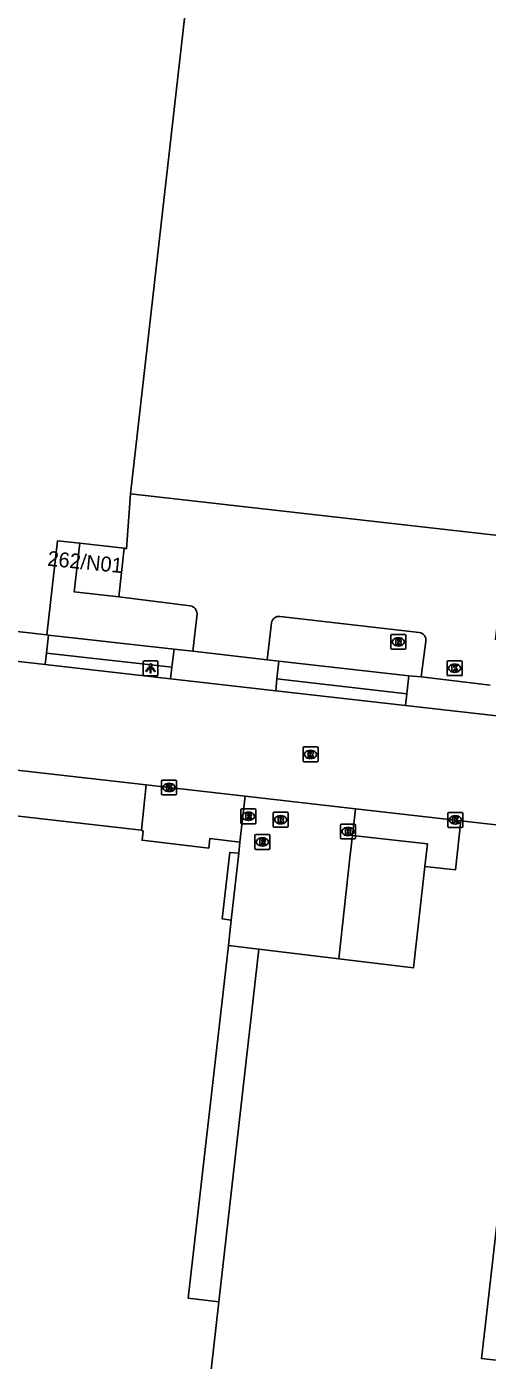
# Model space of a CAD drawing. Extents: x 161389 to 162585, y 388479 to 389761.
# Drawn here: x 162433.2 to 162464.1, y 388747.2 to 388836.7 of the extents above; entities that cross this region are included whole.
import ezdxf

# ---------------------------------------------------------------- set-up
doc = ezdxf.new("R2010")
doc.units = 0
for name, color, linetype in [('IMGEO_Groenvoorziening', 7, 'Continuous'), ('IMGEO_Kolk', 7, 'Continuous'), ('IMGEO_Lichtpunt', 7, 'Continuous'), ('IMGEO_Pand', 7, 'Continuous'), ('IMGEO_Pand_nummerreeks', 7, 'Continuous'), ('IMGEO_Pand_overbouw', 7, 'Continuous'), ('IMGEO_Parkeervlak_open', 7, 'Continuous'), ('IMGEO_Rijbaan_lokaal_gesloten', 7, 'Continuous'), ('IMGEO_Rioolput', 7, 'Continuous'), ('IMGEO_Voetpad_open', 7, 'Continuous')]:
    doc.layers.add(name, color=color, linetype=linetype)

msp = doc.modelspace()

# ---------------------------------------------------------------- linework, layer by layer
at = {"layer": 'IMGEO_Groenvoorziening'}
for points in [[(162436.753, 388802.017), (162435.263, 388802.18), (162434.552, 388795.859)], [(162459.918, 388780.324), (162461.966, 388780.093), (162462.337, 388783.374)]]:
    msp.add_lwpolyline(points, dxfattribs=at)
at = {"layer": 'IMGEO_Kolk'}
for p, q in [((162461.414, 388793.197), (162461.414, 388794.049)), ((162461.489, 388794.123), (162462.341, 388794.123)), ((162461.902, 388793.903), (162461.927, 388793.903)), ((162462.415, 388794.049), (162462.415, 388793.197)), ((162462.341, 388793.123), (162461.489, 388793.123)), ((162461.925, 388793.343), (162461.9, 388793.343)), ((162442.249, 388785.195), (162442.249, 388786.047)), ((162442.324, 388786.121), (162443.176, 388786.121)), ((162442.76, 388785.341), (162442.735, 388785.341)), ((162442.737, 388785.901), (162442.762, 388785.901)), ((162443.25, 388786.047), (162443.25, 388785.195)), ((162443.176, 388785.121), (162442.324, 388785.121)), ((162461.462, 388783.018), (162461.462, 388783.87)), ((162461.537, 388783.944), (162462.389, 388783.944)), ((162461.95, 388783.724), (162461.975, 388783.724)), ((162462.463, 388783.87), (162462.463, 388783.018)), ((162462.389, 388782.944), (162461.537, 388782.944)), ((162461.973, 388783.164), (162461.948, 388783.164))]:
    msp.add_line(p, q, dxfattribs=at)
for points in [[(162461.414, 388793.197), (162461.414, 388794.049)], [(162461.489, 388794.123), (162462.341, 388794.123)], [(162461.735, 388793.823), (162461.858, 388793.823), (162461.858, 388793.672), (162461.988, 388793.823), (162462.152, 388793.823), (162462.006, 388793.672), (162462.159, 388793.423), (162462.007, 388793.423), (162461.922, 388793.587), (162461.858, 388793.52), (162461.858, 388793.423), (162461.735, 388793.423), (162461.735, 388793.823)], [(162462.415, 388794.049), (162462.415, 388793.197)], [(162462.341, 388793.123), (162461.489, 388793.123)], [(162442.249, 388785.195), (162442.249, 388786.047)], [(162442.324, 388786.121), (162443.176, 388786.121)], [(162442.57, 388785.821), (162442.693, 388785.821), (162442.693, 388785.67), (162442.823, 388785.821), (162442.987, 388785.821), (162442.841, 388785.67), (162442.994, 388785.421), (162442.842, 388785.421), (162442.757, 388785.585), (162442.693, 388785.518), (162442.693, 388785.421), (162442.57, 388785.421), (162442.57, 388785.821)], [(162443.25, 388786.047), (162443.25, 388785.195)], [(162443.176, 388785.121), (162442.324, 388785.121)], [(162461.462, 388783.018), (162461.462, 388783.87)], [(162461.537, 388783.944), (162462.389, 388783.944)], [(162461.783, 388783.644), (162461.906, 388783.644), (162461.906, 388783.493), (162462.036, 388783.644), (162462.2, 388783.644), (162462.054, 388783.493), (162462.207, 388783.244), (162462.055, 388783.244), (162461.97, 388783.408), (162461.906, 388783.341), (162461.906, 388783.244), (162461.783, 388783.244), (162461.783, 388783.644)], [(162462.463, 388783.87), (162462.463, 388783.018)], [(162462.389, 388782.944), (162461.537, 388782.944)]]:
    msp.add_lwpolyline(points, dxfattribs=at)
for centre, start, end in [((162461.491, 388794.047), 91.55205, 178.44795), ((162461.491, 388794.047), 91.55205, 178.44795), ((162462.339, 388794.047), 1.55205, 88.44795), ((162462.339, 388794.047), 1.55205, 88.44795), ((162461.491, 388793.199), 181.55205, 268.44795), ((162461.491, 388793.199), 181.55205, 268.44795), ((162462.339, 388793.199), 271.55205, 358.44795), ((162462.339, 388793.199), 271.55205, 358.44795), ((162442.326, 388786.045), 91.55205, 178.44795), ((162442.326, 388786.045), 91.55205, 178.44795), ((162443.174, 388786.045), 1.55205, 88.44795), ((162443.174, 388786.045), 1.55205, 88.44795), ((162442.326, 388785.197), 181.55205, 268.44795), ((162442.326, 388785.197), 181.55205, 268.44795), ((162443.174, 388785.197), 271.55205, 358.44795), ((162443.174, 388785.197), 271.55205, 358.44795), ((162461.539, 388783.868), 91.55205, 178.44795), ((162461.539, 388783.868), 91.55205, 178.44795), ((162462.387, 388783.868), 1.55205, 88.44795), ((162462.387, 388783.868), 1.55205, 88.44795), ((162461.539, 388783.02), 181.55205, 268.44795), ((162461.539, 388783.02), 181.55205, 268.44795), ((162462.387, 388783.02), 271.55205, 358.44795), ((162462.387, 388783.02), 271.55205, 358.44795)]:
    msp.add_arc(centre, 0.0765, start, end, dxfattribs=at)
for centre, major_axis, ratio, start_param, end_param in [((162461.901, 388793.623), (-0.387, 0.002), 0.722429, 4.712389, 7.853982), ((162461.926, 388793.623), (-0.39, 0.002), 0.717154, 1.570796, 4.712389), ((162442.736, 388785.621), (-0.387, 0.002), 0.722429, 4.712389, 7.853982), ((162442.761, 388785.621), (-0.39, 0.002), 0.717154, 1.570796, 4.712389), ((162461.949, 388783.444), (-0.387, 0.002), 0.722429, 4.712389, 7.853982), ((162461.974, 388783.444), (-0.39, 0.002), 0.717154, 1.570796, 4.712389)]:
    msp.add_ellipse(centre, major_axis=major_axis, ratio=ratio, start_param=start_param, end_param=end_param, dxfattribs=at)
at = {"layer": 'IMGEO_Lichtpunt'}
for p, q in [((162441.005, 388794.019), (162441.005, 388793.212)), ((162441.005, 388794.019), (162441.005, 388793.212)), ((162441.907, 388794.114), (162441.099, 388794.114)), ((162441.907, 388794.114), (162441.099, 388794.114)), ((162442.001, 388793.212), (162442.001, 388794.019)), ((162442.001, 388793.212), (162442.001, 388794.019)), ((162441.099, 388793.118), (162441.907, 388793.118)), ((162441.099, 388793.118), (162441.907, 388793.118))]:
    msp.add_line(p, q, dxfattribs=at)
for points in [[(162441.379, 388793.683), (162441.418, 388793.655), (162441.23, 388793.393), (162441.192, 388793.42), (162441.379, 388793.683)], [(162441.481, 388793.635), (162441.528, 388793.635), (162441.528, 388793.313), (162441.481, 388793.313), (162441.481, 388793.635)], [(162441.591, 388793.655), (162441.629, 388793.682), (162441.816, 388793.42), (162441.777, 388793.392), (162441.591, 388793.655)]]:
    msp.add_lwpolyline(points, dxfattribs=at)
msp.add_circle((162441.504, 388793.817), 0.0994, dxfattribs=at)
for centre, start, end in [((162441.099, 388794.019), 90, 180), ((162441.099, 388794.019), 90, 180), ((162441.907, 388794.019), 0, 90), ((162441.907, 388794.019), 0, 90), ((162441.099, 388793.212), 180, 270), ((162441.099, 388793.212), 180, 270), ((162441.907, 388793.212), 270, 0), ((162441.907, 388793.212), 270, 360)]:
    msp.add_arc(centre, 0.0946, start, end, dxfattribs=at)
at = {"layer": 'IMGEO_Pand'}
for points in [[(162440.168, 388805.317), (162445.286, 388850.441), (162482.306, 388846.26), (162482.466, 388837.077), (162482.487, 388836.004), (162487.823, 388836.098), (162489.492, 388836.131)], [(162440.168, 388805.317), (162465.452, 388802.451), (162464.664, 388795.518)], [(162439.367, 388798.403), (162436.385, 388798.738), (162436.753, 388802.017)], [(162436.753, 388802.017), (162439.735, 388801.682)], [(162439.735, 388801.682), (162439.367, 388798.403)], [(162440.896, 388782.752), (162414.734, 388785.722)], [(162447.5, 388781.959), (162445.494, 388782.197), (162445.411, 388781.558), (162440.936, 388782.073), (162441.007, 388782.699), (162440.896, 388782.752)], [(162447.5, 388781.959), (162447.432, 388781.205)], [(162446.92, 388776.723), (162446.311, 388776.801), (162446.824, 388781.26), (162447.432, 388781.205)], [(162484.257, 388737.573), (162484.131, 388744.901), (162484.124, 388745.295), (162484.388, 388745.288), (162484.585, 388747.086), (162480.19, 388747.631), (162479.955, 388745.444), (162463.726, 388747.292), (162464.034, 388750), (162466.634, 388772.833), (162483.618, 388770.935), (162483.585, 388770.043), (162488.919, 388770.194), (162488.998, 388770.12), (162491.396, 388770.192), (162492.166, 388776.206), (162489.637, 388776.512), (162489.631, 388777.339)], [(162446.92, 388776.723), (162446.744, 388775.005)], [(162446.744, 388775.005), (162444.021, 388751.356), (162446.098, 388751.105), (162443.362, 388726.917), (162438.974, 388727.412)]]:
    msp.add_lwpolyline(points, dxfattribs=at)
at = {"layer": 'IMGEO_Pand_overbouw'}
for points in [[(162447.432, 388781.205), (162446.824, 388781.26), (162446.311, 388776.801), (162446.92, 388776.723)], [(162446.098, 388751.105), (162448.766, 388774.777), (162446.744, 388775.005), (162444.021, 388751.356)]]:
    msp.add_lwpolyline(points, close=True, dxfattribs=at)
at = {"layer": 'IMGEO_Parkeervlak_open'}
for points in [[(162439.735, 388801.682), (162439.879, 388801.637), (162440.168, 388805.317)], [(162444.17, 388797.808), (162439.367, 388798.403)], [(162444.338, 388794.771), (162444.626, 388797.272)], [(162450.197, 388797.095), (162459.544, 388796.016)], [(162449.338, 388794.177), (162449.624, 388796.661)], [(162459.984, 388795.44), (162459.672, 388793.036)], [(162455.059, 388782.406), (162460.087, 388781.849), (162459.918, 388780.324)], [(162454.133, 388774.13), (162459.164, 388773.524), (162459.918, 388780.324)]]:
    msp.add_lwpolyline(points, dxfattribs=at)
for centre, radius, start, end in [((162444.089, 388797.277), 0.537, 359.47863, 81.30007), ((162450.123, 388796.597), 0.503, 81.58842, 172.6934), ((162459.485, 388795.515), 0.505, 351.49134, 83.26028)]:
    msp.add_arc(centre, radius, start, end, dxfattribs=at)
at = {"layer": 'IMGEO_Rijbaan_lokaal_gesloten'}
for points in [[(162434.425, 388793.87), (162423.146, 388795.15)], [(162442.854, 388792.912), (162434.425, 388793.87)], [(162449.905, 388792.112), (162442.854, 388792.912)], [(162458.615, 388791.123), (162449.905, 388792.112)], [(162464.75, 388790.426), (162458.615, 388791.123)], [(162415.064, 388788.76), (162424.047, 388787.734), (162441.217, 388785.796)], [(162441.217, 388785.796), (162442.75, 388785.623), (162447.857, 388785.036)], [(162447.857, 388785.036), (162455.264, 388784.185)], [(162455.264, 388784.185), (162461.961, 388783.416), (162462.337, 388783.374)], [(162462.337, 388783.374), (162471.602, 388782.341)]]:
    msp.add_lwpolyline(points, dxfattribs=at)
at = {"layer": 'IMGEO_Rioolput'}
for p, q in [((162457.635, 388794.966), (162457.635, 388795.818)), ((162457.71, 388795.892), (162458.562, 388795.892)), ((162458.123, 388795.672), (162458.148, 388795.672)), ((162458.636, 388795.818), (162458.636, 388794.966)), ((162458.562, 388794.892), (162457.71, 388794.892)), ((162458.146, 388795.112), (162458.121, 388795.112)), ((162451.743, 388787.412), (162451.743, 388788.264)), ((162451.818, 388788.338), (162452.67, 388788.338)), ((162452.231, 388788.118), (162452.256, 388788.118)), ((162452.744, 388788.264), (162452.744, 388787.412)), ((162452.67, 388787.338), (162451.818, 388787.338)), ((162452.254, 388787.558), (162452.229, 388787.558)), ((162447.573, 388783.26), (162447.573, 388784.112)), ((162447.648, 388784.186), (162448.5, 388784.186)), ((162448.061, 388783.966), (162448.086, 388783.966)), ((162448.574, 388784.112), (162448.574, 388783.26)), ((162449.737, 388783.03), (162449.737, 388783.882)), ((162449.812, 388783.956), (162450.664, 388783.956)), ((162450.225, 388783.736), (162450.25, 388783.736)), ((162450.738, 388783.882), (162450.738, 388783.03)), ((162448.5, 388783.186), (162447.648, 388783.186)), ((162448.084, 388783.406), (162448.059, 388783.406)), ((162450.664, 388782.956), (162449.812, 388782.956)), ((162450.248, 388783.176), (162450.223, 388783.176)), ((162454.26, 388782.239), (162454.26, 388783.091)), ((162454.335, 388783.165), (162455.187, 388783.165)), ((162454.748, 388782.945), (162454.773, 388782.945)), ((162455.261, 388783.091), (162455.261, 388782.239)), ((162448.513, 388781.538), (162448.513, 388782.39)), ((162448.588, 388782.464), (162449.44, 388782.464)), ((162449.001, 388782.244), (162449.026, 388782.244)), ((162449.514, 388782.39), (162449.514, 388781.538)), ((162455.187, 388782.165), (162454.335, 388782.165)), ((162454.771, 388782.385), (162454.746, 388782.385)), ((162449.44, 388781.464), (162448.588, 388781.464)), ((162449.024, 388781.684), (162448.999, 388781.684))]:
    msp.add_line(p, q, dxfattribs=at)
for points in [[(162457.635, 388794.966), (162457.635, 388795.818)], [(162457.71, 388795.892), (162458.562, 388795.892)], [(162458.224, 388795.59), (162457.972, 388795.592), (162457.972, 388795.192)], [(162457.972, 388795.192), (162458.096, 388795.192), (162458.096, 388795.354), (162458.107, 388795.354)], [(162458.15, 388795.511), (162458.096, 388795.511), (162458.096, 388795.43)], [(162458.096, 388795.43), (162458.148, 388795.43)], [(162458.154, 388795.325), (162458.225, 388795.192), (162458.365, 388795.192), (162458.3, 388795.318)], [(162458.636, 388795.818), (162458.636, 388794.966)], [(162458.562, 388794.892), (162457.71, 388794.892)], [(162451.743, 388787.412), (162451.743, 388788.264)], [(162451.818, 388788.338), (162452.67, 388788.338)], [(162452.332, 388788.036), (162452.08, 388788.038), (162452.08, 388787.638)], [(162452.744, 388788.264), (162452.744, 388787.412)], [(162452.67, 388787.338), (162451.818, 388787.338)], [(162452.08, 388787.638), (162452.204, 388787.638), (162452.204, 388787.8), (162452.215, 388787.8)], [(162452.258, 388787.957), (162452.204, 388787.957), (162452.204, 388787.876)], [(162452.204, 388787.876), (162452.256, 388787.876)], [(162452.262, 388787.771), (162452.333, 388787.638), (162452.473, 388787.638), (162452.408, 388787.764)], [(162447.573, 388783.26), (162447.573, 388784.112)], [(162447.648, 388784.186), (162448.5, 388784.186)], [(162448.162, 388783.884), (162447.91, 388783.886), (162447.91, 388783.486)], [(162447.91, 388783.486), (162448.034, 388783.486), (162448.034, 388783.648), (162448.045, 388783.648)], [(162448.088, 388783.805), (162448.034, 388783.805), (162448.034, 388783.724)], [(162448.034, 388783.724), (162448.086, 388783.724)], [(162448.092, 388783.619), (162448.163, 388783.486), (162448.303, 388783.486), (162448.238, 388783.612)], [(162448.574, 388784.112), (162448.574, 388783.26)], [(162449.737, 388783.03), (162449.737, 388783.882)], [(162449.812, 388783.956), (162450.664, 388783.956)], [(162450.326, 388783.654), (162450.074, 388783.656), (162450.074, 388783.256)], [(162450.252, 388783.575), (162450.198, 388783.575), (162450.198, 388783.494)], [(162450.738, 388783.882), (162450.738, 388783.03)], [(162448.5, 388783.186), (162447.648, 388783.186)], [(162450.664, 388782.956), (162449.812, 388782.956)], [(162450.074, 388783.256), (162450.198, 388783.256), (162450.198, 388783.418), (162450.209, 388783.418)], [(162450.198, 388783.494), (162450.25, 388783.494)], [(162450.256, 388783.389), (162450.327, 388783.256), (162450.467, 388783.256), (162450.402, 388783.382)], [(162454.26, 388782.239), (162454.26, 388783.091)], [(162454.335, 388783.165), (162455.187, 388783.165)], [(162454.849, 388782.863), (162454.597, 388782.865), (162454.597, 388782.465)], [(162454.597, 388782.465), (162454.721, 388782.465), (162454.721, 388782.627), (162454.732, 388782.627)], [(162454.775, 388782.784), (162454.721, 388782.784), (162454.721, 388782.703)], [(162454.721, 388782.703), (162454.773, 388782.703)], [(162455.261, 388783.091), (162455.261, 388782.239)], [(162448.513, 388781.538), (162448.513, 388782.39)], [(162448.588, 388782.464), (162449.44, 388782.464)], [(162449.102, 388782.162), (162448.85, 388782.164), (162448.85, 388781.764)], [(162448.85, 388781.764), (162448.974, 388781.764), (162448.974, 388781.926), (162448.985, 388781.926)], [(162449.028, 388782.083), (162448.974, 388782.083), (162448.974, 388782.002)], [(162448.974, 388782.002), (162449.026, 388782.002)], [(162449.032, 388781.897), (162449.103, 388781.764), (162449.243, 388781.764), (162449.178, 388781.89)], [(162449.514, 388782.39), (162449.514, 388781.538)], [(162455.187, 388782.165), (162454.335, 388782.165)], [(162454.779, 388782.598), (162454.85, 388782.465), (162454.99, 388782.465), (162454.925, 388782.591)], [(162449.44, 388781.464), (162448.588, 388781.464)]]:
    msp.add_lwpolyline(points, dxfattribs=at)
for centre, radius, start, end in [((162457.712, 388795.816), 0.0765, 91.55205, 178.44795), ((162457.712, 388795.816), 0.0765, 91.55205, 178.44795), ((162458.106, 388795.301), 0.0533, 26.02933, 88.69889), ((162458.132, 388795.619), 0.19, 274.7715, 282.96867), ((162458.156, 388795.415), 0.0964, 77.00612, 93.18647), ((162458.17, 388795.472), 0.0378, 276.66336, 79.67722), ((162458.223, 388795.48), 0.109, 350.36119, 89.41601), ((162458.221, 388795.48), 0.112, 277.58423, 350.98172), ((162458.205, 388795.265), 0.108, 29.51342, 73.79051), ((162458.56, 388795.816), 0.0765, 1.55205, 88.44795), ((162458.56, 388795.816), 0.0765, 1.55205, 88.44795), ((162457.712, 388794.968), 0.0765, 181.55205, 268.44795), ((162457.712, 388794.968), 0.0765, 181.55205, 268.44795), ((162458.56, 388794.968), 0.0765, 271.55205, 358.44795), ((162458.56, 388794.968), 0.0765, 271.55205, 358.44795), ((162451.82, 388788.262), 0.0765, 91.55205, 178.44795), ((162451.82, 388788.262), 0.0765, 91.55205, 178.44795), ((162452.331, 388787.926), 0.109, 350.36119, 89.41601), ((162452.668, 388788.262), 0.0765, 1.55205, 88.44795), ((162452.668, 388788.262), 0.0765, 1.55205, 88.44795), ((162451.82, 388787.414), 0.0765, 181.55205, 268.44795), ((162451.82, 388787.414), 0.0765, 181.55205, 268.44795), ((162452.214, 388787.747), 0.0533, 26.02933, 88.69889), ((162452.24, 388788.065), 0.19, 274.7715, 282.96867), ((162452.264, 388787.861), 0.0964, 77.00612, 93.18647), ((162452.278, 388787.918), 0.0378, 276.66336, 79.67722), ((162452.329, 388787.926), 0.112, 277.58423, 350.98172), ((162452.313, 388787.711), 0.108, 29.51342, 73.79051), ((162452.668, 388787.414), 0.0765, 271.55205, 358.44795), ((162452.668, 388787.414), 0.0765, 271.55205, 358.44795), ((162447.65, 388784.11), 0.0765, 91.55205, 178.44795), ((162447.65, 388784.11), 0.0765, 91.55205, 178.44795), ((162448.044, 388783.595), 0.0533, 26.02933, 88.69889), ((162448.07, 388783.913), 0.19, 274.7715, 282.96867), ((162448.094, 388783.709), 0.0964, 77.00612, 93.18647), ((162448.108, 388783.766), 0.0378, 276.66336, 79.67722), ((162448.161, 388783.774), 0.109, 350.36119, 89.41601), ((162448.159, 388783.774), 0.112, 277.58423, 350.98172), ((162448.143, 388783.559), 0.108, 29.51342, 73.79051), ((162448.498, 388784.11), 0.0765, 1.55205, 88.44795), ((162448.498, 388784.11), 0.0765, 1.55205, 88.44795), ((162449.814, 388783.88), 0.0765, 91.55205, 178.44795), ((162449.814, 388783.88), 0.0765, 91.55205, 178.44795), ((162450.258, 388783.479), 0.0964, 77.00612, 93.18647), ((162450.272, 388783.536), 0.0378, 276.66336, 79.67722), ((162450.325, 388783.544), 0.109, 350.36119, 89.41601), ((162450.323, 388783.544), 0.112, 277.58423, 350.98172), ((162450.662, 388783.88), 0.0765, 1.55205, 88.44795), ((162450.662, 388783.88), 0.0765, 1.55205, 88.44795), ((162447.65, 388783.262), 0.0765, 181.55205, 268.44795), ((162447.65, 388783.262), 0.0765, 181.55205, 268.44795), ((162448.498, 388783.262), 0.0765, 271.55205, 358.44795), ((162448.498, 388783.262), 0.0765, 271.55205, 358.44795), ((162449.814, 388783.032), 0.0765, 181.55205, 268.44795), ((162449.814, 388783.032), 0.0765, 181.55205, 268.44795), ((162450.208, 388783.365), 0.0533, 26.02933, 88.69889), ((162450.234, 388783.683), 0.19, 274.7715, 282.96867), ((162450.307, 388783.329), 0.108, 29.51342, 73.79051), ((162450.662, 388783.032), 0.0765, 271.55205, 358.44795), ((162450.662, 388783.032), 0.0765, 271.55205, 358.44795), ((162454.337, 388783.089), 0.0765, 91.55205, 178.44795), ((162454.337, 388783.089), 0.0765, 91.55205, 178.44795), ((162454.731, 388782.574), 0.0533, 26.02933, 88.69889), ((162454.757, 388782.892), 0.19, 274.7715, 282.96867), ((162454.781, 388782.688), 0.0964, 77.00612, 93.18647), ((162454.795, 388782.745), 0.0378, 276.66336, 79.67722), ((162454.848, 388782.753), 0.109, 350.36119, 89.41601), ((162454.846, 388782.753), 0.112, 277.58423, 350.98172), ((162454.83, 388782.538), 0.108, 29.51342, 73.79051), ((162455.185, 388783.089), 0.0765, 1.55205, 88.44795), ((162455.185, 388783.089), 0.0765, 1.55205, 88.44795), ((162448.59, 388782.388), 0.0765, 91.55205, 178.44795), ((162448.59, 388782.388), 0.0765, 91.55205, 178.44795), ((162448.984, 388781.873), 0.0533, 26.02933, 88.69889), ((162449.01, 388782.191), 0.19, 274.7715, 282.96867), ((162449.034, 388781.987), 0.0964, 77.00612, 93.18647), ((162449.048, 388782.044), 0.0378, 276.66336, 79.67722), ((162449.101, 388782.052), 0.109, 350.36119, 89.41601), ((162449.099, 388782.052), 0.112, 277.58423, 350.98172), ((162449.083, 388781.837), 0.108, 29.51342, 73.79051), ((162449.438, 388782.388), 0.0765, 1.55205, 88.44795), ((162449.438, 388782.388), 0.0765, 1.55205, 88.44795), ((162454.337, 388782.241), 0.0765, 181.55205, 268.44795), ((162454.337, 388782.241), 0.0765, 181.55205, 268.44795), ((162455.185, 388782.241), 0.0765, 271.55205, 358.44795), ((162455.185, 388782.241), 0.0765, 271.55205, 358.44795), ((162448.59, 388781.54), 0.0765, 181.55205, 268.44795), ((162448.59, 388781.54), 0.0765, 181.55205, 268.44795), ((162449.438, 388781.54), 0.0765, 271.55205, 358.44795), ((162449.438, 388781.54), 0.0765, 271.55205, 358.44795)]:
    msp.add_arc(centre, radius, start, end, dxfattribs=at)
for centre, major_axis, ratio, start_param, end_param in [((162458.122, 388795.392), (-0.387, 0.002), 0.722429, 4.712389, 7.853982), ((162458.147, 388795.392), (-0.39, 0.002), 0.717154, 1.570796, 4.712389), ((162452.23, 388787.838), (-0.387, 0.002), 0.722429, 4.712389, 7.853982), ((162452.255, 388787.838), (-0.39, 0.002), 0.717154, 1.570796, 4.712389), ((162448.06, 388783.686), (-0.387, 0.002), 0.722429, 4.712389, 7.853982), ((162448.085, 388783.686), (-0.39, 0.002), 0.717154, 1.570796, 4.712389), ((162450.224, 388783.456), (-0.387, 0.002), 0.722429, 4.712389, 7.853982), ((162450.249, 388783.456), (-0.39, 0.002), 0.717154, 1.570796, 4.712389), ((162454.747, 388782.665), (-0.387, 0.002), 0.722429, 4.712389, 7.853982), ((162454.772, 388782.665), (-0.39, 0.002), 0.717154, 1.570796, 4.712389), ((162449, 388781.964), (-0.387, 0.002), 0.722429, 4.712389, 7.853982), ((162449.025, 388781.964), (-0.39, 0.002), 0.717154, 1.570796, 4.712389)]:
    msp.add_ellipse(centre, major_axis=major_axis, ratio=ratio, start_param=start_param, end_param=end_param, dxfattribs=at)
at = {"layer": 'IMGEO_Voetpad_open'}
for points in [[(162434.552, 388795.859), (162423.214, 388797.141)], [(162434.65, 388795.848), (162434.513, 388794.642)], [(162434.552, 388795.859), (162434.65, 388795.848)], [(162434.65, 388795.848), (162443.078, 388794.899)], [(162434.425, 388793.87), (162434.513, 388794.642)], [(162434.513, 388794.642), (162442.943, 388793.684)], [(162442.943, 388793.684), (162443.078, 388794.899)], [(162443.078, 388794.899), (162444.338, 388794.771)], [(162444.338, 388794.771), (162449.338, 388794.177)], [(162442.854, 388792.912), (162442.943, 388793.684)], [(162449.338, 388794.177), (162450.111, 388794.107)], [(162450.111, 388794.107), (162449.978, 388792.905)], [(162450.111, 388794.107), (162458.846, 388793.115)], [(162449.978, 388792.905), (162449.905, 388792.112)], [(162458.713, 388791.9), (162449.978, 388792.905)], [(162458.846, 388793.115), (162458.713, 388791.9)], [(162458.846, 388793.115), (162459.672, 388793.036)], [(162459.672, 388793.036), (162464.296, 388792.481)], [(162458.615, 388791.123), (162458.713, 388791.9)], [(162441.217, 388785.796), (162440.896, 388782.752)], [(162447.857, 388785.036), (162447.5, 388781.959)], [(162455.264, 388784.185), (162455.059, 388782.406)], [(162455.059, 388782.406), (162454.885, 388780.897), (162454.133, 388774.13)], [(162447.432, 388781.205), (162446.92, 388776.723)], [(162454.133, 388774.13), (162448.766, 388774.777), (162446.744, 388775.005)]]:
    msp.add_lwpolyline(points, dxfattribs=at)

# ---------------------------------------------------------------- texts
at = {"layer": 'IMGEO_Pand_nummerreeks'}
msp.add_text('262/N01', height=1, rotation=354.31629, dxfattribs=at).set_placement((162434.549, 388800.505))

doc.saveas('drawing.dxf')
